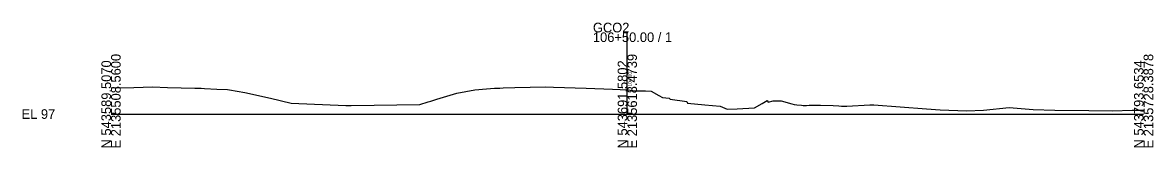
# Model space of a CAD drawing. Extents: x -14327 to 8886, y -10 to 39048.
# Drawn here: x 3974.3 to 4302.8, y 32990.3 to 33026.6 of the extents above; entities that cross this region are included whole.
import ezdxf

# ---------------------------------------------------------------- set-up
doc = ezdxf.new("R2010")
doc.units = 0
for name, color, linetype in [('RD_GPK_XS_Cell', 7, 'Continuous'), ('RD_XS_ExGround', 7, 'Continuous'), ('RD_XS_TX_Elev_EX', 7, 'Continuous')]:
    doc.layers.add(name, color=color, linetype=linetype)

msp = doc.modelspace()

# ---------------------------------------------------------------- linework, layer by layer
at = {"layer": 'RD_GPK_XS_Cell'}
for p, q in [((4150, 33000), (4150, 33023.73)), ((4000, 33000), (4150, 33000)), ((4150, 33000), (4300, 33000))]:
    msp.add_line(p, q, dxfattribs=at)
at = {"layer": 'RD_XS_ExGround'}
for p, q in [((4000.18, 33007.61), (4006.66, 33007.75)), ((4006.66, 33007.75), (4012.03, 33007.89)), ((4012.03, 33007.89), (4016.36, 33007.76)), ((4016.36, 33007.76), (4024.37, 33007.56)), ((4117.35, 33007.67), (4126.22, 33007.91)), ((4126.22, 33007.91), (4128.58, 33007.84)), ((4128.58, 33007.84), (4138.07, 33007.56)), ((4000, 33007.6), (4000.18, 33007.61)), ((4024.37, 33007.56), (4026.16, 33007.51)), ((4026.16, 33007.51), (4027.14, 33007.46)), ((4027.14, 33007.46), (4030.69, 33007.26)), ((4030.69, 33007.26), (4033.88, 33007.12)), ((4033.88, 33007.12), (4034.46, 33007.03)), ((4034.46, 33007.03), (4038.91, 33006.22)), ((4038.91, 33006.22), (4046.3, 33004.58)), ((4046.3, 33004.58), (4052.35, 33003.12)), ((4094.67, 33004.29), (4100.5, 33006.1)), ((4100.5, 33006.1), (4105.72, 33007.05)), ((4105.72, 33007.05), (4109.1, 33007.34)), ((4109.1, 33007.34), (4111.43, 33007.49)), ((4111.43, 33007.49), (4112.96, 33007.54)), ((4112.96, 33007.54), (4113.96, 33007.57)), ((4113.96, 33007.57), (4117.35, 33007.67)), ((4138.07, 33007.56), (4145.72, 33007.27)), ((4145.72, 33007.27), (4147.91, 33007.16)), ((4147.91, 33007.16), (4150.12, 33006.99)), ((4150.12, 33006.99), (4152.23, 33006.73)), ((4152.23, 33006.73), (4155.24, 33006.7)), ((4155.24, 33006.7), (4156.96, 33006.61)), ((4156.96, 33006.61), (4159.18, 33005.35)), ((4159.18, 33005.35), (4160.22, 33004.77)), ((4160.22, 33004.77), (4162.15, 33004.59)), ((4162.15, 33004.59), (4162.45, 33004.29)), ((4052.35, 33003.12), (4068.24, 33002.53)), ((4068.24, 33002.53), (4069.02, 33002.5)), ((4069.02, 33002.5), (4069.79, 33002.52)), ((4069.79, 33002.52), (4089.75, 33002.81)), ((4089.75, 33002.81), (4092.17, 33003.52)), ((4092.17, 33003.52), (4092.89, 33003.74)), ((4092.89, 33003.74), (4094.12, 33004.13)), ((4094.12, 33004.13), (4094.67, 33004.29)), ((4162.45, 33004.29), (4167.28, 33003.63)), ((4167.28, 33003.63), (4167.46, 33003.12)), ((4167.46, 33003.12), (4172.56, 33002.67)), ((4172.56, 33002.67), (4176.96, 33002.32)), ((4176.96, 33002.32), (4178.33, 33001.71)), ((4178.33, 33001.71), (4179.03, 33001.41)), ((4179.03, 33001.41), (4181.9, 33001.54)), ((4181.9, 33001.54), (4186.97, 33001.83)), ((4186.97, 33001.83), (4189.15, 33003.02)), ((4189.15, 33003.02), (4190.65, 33003.91)), ((4190.65, 33003.91), (4190.88, 33003.42)), ((4190.88, 33003.42), (4192.38, 33003.88)), ((4192.38, 33003.88), (4194.71, 33003.85)), ((4194.71, 33003.85), (4197.78, 33003)), ((4197.78, 33003), (4198.44, 33002.82)), ((4198.44, 33002.82), (4199.2, 33002.65)), ((4199.2, 33002.65), (4200.58, 33002.54)), ((4200.58, 33002.54), (4201.05, 33002.52)), ((4201.05, 33002.52), (4202.05, 33002.52)), ((4202.05, 33002.52), (4202.82, 33002.56)), ((4202.82, 33002.56), (4204.89, 33002.6)), ((4204.89, 33002.6), (4206.1, 33002.57)), ((4206.1, 33002.57), (4209.78, 33002.53)), ((4209.78, 33002.53), (4211.46, 33002.43)), ((4211.46, 33002.43), (4212.25, 33002.3)), ((4212.25, 33002.3), (4212.66, 33002.25)), ((4212.66, 33002.25), (4213.14, 33002.28)), ((4213.14, 33002.28), (4213.73, 33002.31)), ((4213.73, 33002.31), (4220.5, 33002.68)), ((4220.5, 33002.68), (4221.61, 33002.64)), ((4221.61, 33002.64), (4236.96, 33001.54)), ((4236.96, 33001.54), (4240.92, 33001.2)), ((4240.92, 33001.2), (4248.52, 33000.93)), ((4253.53, 33001.08), (4260.93, 33001.94)), ((4260.93, 33001.94), (4267.87, 33001.34)), ((4267.87, 33001.34), (4274.2, 33001.17)), ((4274.2, 33001.17), (4284.05, 33001.07)), ((4290.95, 33000.97), (4296.64, 33001.13)), ((4296.64, 33001.13), (4300, 33001.08)), ((4248.52, 33000.93), (4253.53, 33001.08)), ((4284.05, 33001.07), (4290.95, 33000.97))]:
    msp.add_line(p, q, dxfattribs=at)

# ---------------------------------------------------------------- texts
at = {"layer": 'RD_GPK_XS_Cell'}
for s, p in [('GCO2', (4140, 33023.73)), ('106+50.00 / 1', (4140, 33020.93)), ('EL 97', (3974, 32998.6))]:
    msp.add_text(s, height=2.8, dxfattribs=at).set_placement(p)
for s, p in [('N 543589.5070', (4000, 32990)), ('E 2135508.5600', (4002.8, 32990)), ('N 543691.5802', (4150, 32990)), ('E 2135618.4739', (4152.8, 32990)), ('N 543793.6534', (4300, 32990)), ('E 2135728.3878', (4302.8, 32990))]:
    msp.add_text(s, height=2.8, rotation=90, dxfattribs=at).set_placement(p)
at = {"layer": 'RD_XS_TX_Elev_EX'}
msp.add_text('104.00', height=1, rotation=90, dxfattribs=at).set_placement((4151.25, 33008))

doc.saveas('drawing.dxf')
